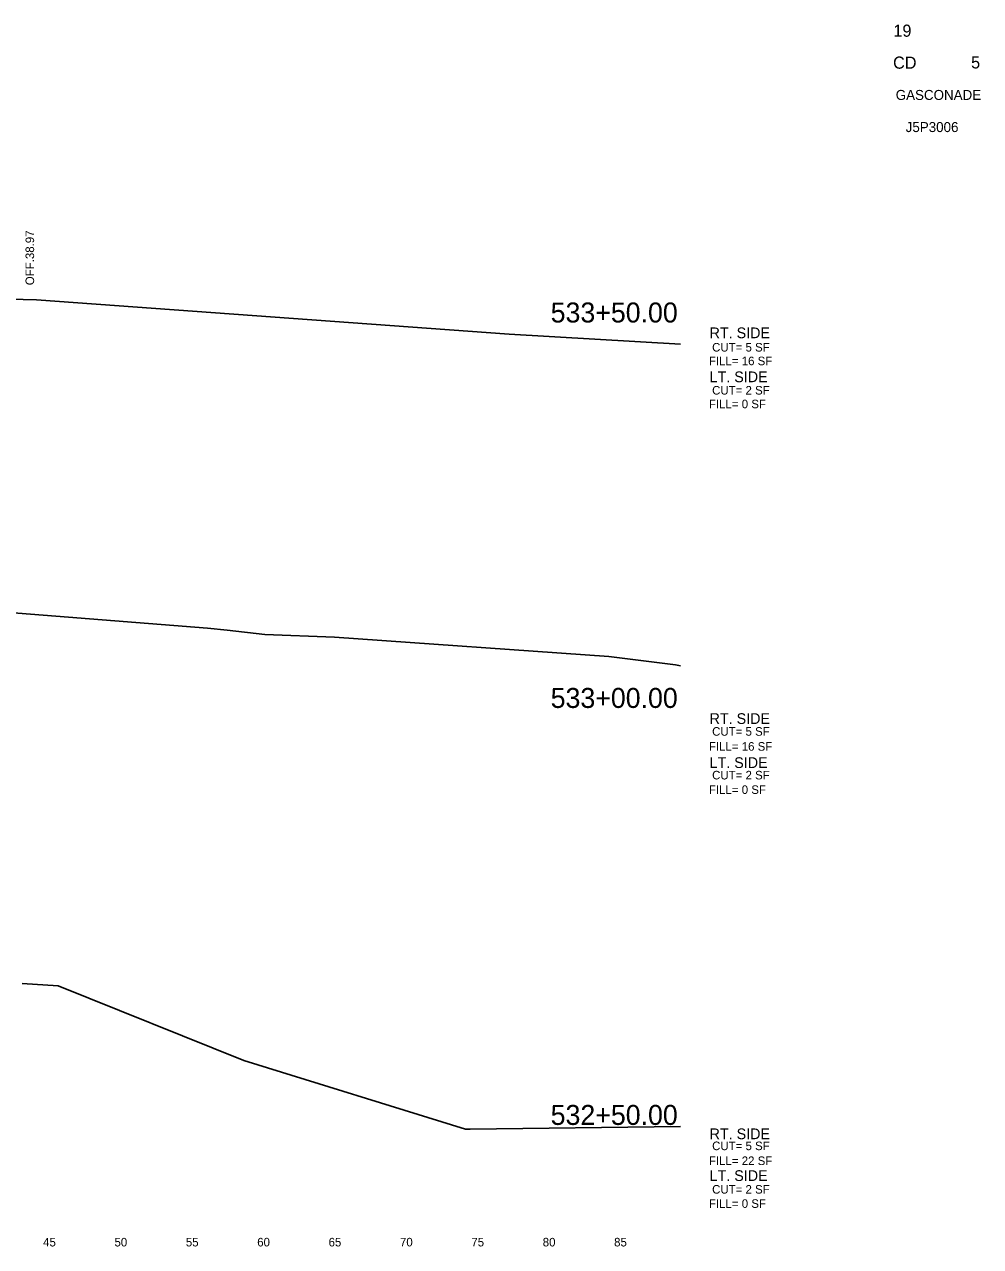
# Model space of a CAD drawing. Extents: x -4 to 359, y 0 to 1436.
# Drawn here: x 87.2 to 154.2, y 600.5 to 686.1 of the extents above; entities that cross this region are included whole.
import ezdxf

# ---------------------------------------------------------------- set-up
doc = ezdxf.new("R2010")
doc.units = 0
for name, color, linetype in [('Common-Title block info', 7, 'Continuous'), ('XS-Existing surface-ground', 7, 'Continuous'), ('XS-Text-earthwork labels', 7, 'Continuous'), ('XS-Text-offset label', 7, 'Continuous'), ('XS-Text-tie elevation', 7, 'Continuous')]:
    doc.layers.add(name, color=color, linetype=linetype)

msp = doc.modelspace()

# ---------------------------------------------------------------- linework, layer by layer
at = {"layer": 'XS-Existing surface-ground'}
for p, q in [((84.816, 666.868), (88.02, 666.783)), ((88.02, 666.783), (121.124, 664.368)), ((121.124, 664.368), (133.13, 663.672)), ((81.884, 645.206), (100.006, 643.781)), ((100.006, 643.781), (101.384, 643.654)), ((101.384, 643.654), (104.005, 643.345)), ((104.005, 643.345), (108.9, 643.149)), ((108.9, 643.149), (128.11, 641.794)), ((128.11, 641.794), (132.794, 641.229)), ((132.794, 641.229), (133.13, 641.145)), ((87.015, 618.901), (89.541, 618.729)), ((89.541, 618.729), (102.537, 613.504)), ((102.537, 613.504), (118.076, 608.704)), ((118.076, 608.704), (118.402, 608.694)), ((118.402, 608.694), (133.13, 608.887))]:
    msp.add_line(p, q, dxfattribs=at)

# ---------------------------------------------------------------- texts
at = {"layer": 'Common-Title block info'}
for s, height, p in [('19', 0.85, (148.047, 685.208)), ('CD', 0.85, (148.025, 682.97)), ('5', 0.85, (153.491, 682.988)), ('GASCONADE', 0.7, (148.211, 680.783)), ('J5P3006', 0.7, (148.909, 678.533))]:
    msp.add_text(s, height=height, dxfattribs=at).set_placement(p)
at = {"layer": 'XS-Text-earthwork labels'}
for s, height, p in [('RT. SIDE', 0.75, (135.171, 664.095)), (' CUT= 5 SF           ', 0.6, (135.125, 663.161)), ('FILL= 16 SF           ', 0.6, (135.125, 662.201)), ('LT. SIDE', 0.75, (135.171, 661.014)), (' CUT= 2 SF           ', 0.6, (135.125, 660.147)), ('FILL= 0 SF           ', 0.6, (135.125, 659.187)), ('RT. SIDE', 0.75, (135.171, 637.078)), (' CUT= 5 SF           ', 0.6, (135.125, 636.252)), ('FILL= 16 SF           ', 0.6, (135.125, 635.204)), ('LT. SIDE', 0.75, (135.171, 633.992)), (' CUT= 2 SF           ', 0.6, (135.125, 633.192)), ('FILL= 0 SF           ', 0.6, (135.125, 632.175)), ('RT. SIDE', 0.75, (135.171, 607.994)), (' CUT= 5 SF           ', 0.6, (135.125, 607.226)), ('FILL= 22 SF           ', 0.6, (135.125, 606.183)), ('LT. SIDE', 0.75, (135.171, 605.068)), (' CUT= 2 SF           ', 0.6, (135.125, 604.181)), ('FILL= 0 SF           ', 0.6, (135.125, 603.184))]:
    msp.add_text(s, height=height, dxfattribs=at).set_placement(p)
at = {"layer": 'XS-Text-offset label'}
for s, height, p in [('           533+50.00           ', 1.4, (118.317, 665.195)), ('           533+00.00           ', 1.4, (118.317, 638.198)), ('           532+50.00           ', 1.4, (118.317, 608.993)), ('           45           ', 0.6, (86.03, 600.482)), ('           50           ', 0.6, (91.03, 600.482)), ('           55           ', 0.6, (96.03, 600.482)), ('           60           ', 0.6, (101.03, 600.482)), ('           65           ', 0.6, (106.03, 600.482)), ('           70           ', 0.6, (111.03, 600.482)), ('           75           ', 0.6, (116.03, 600.482)), ('           80           ', 0.6, (121.03, 600.482)), ('           85           ', 0.6, (126.03, 600.482))]:
    msp.add_text(s, height=height, dxfattribs=at).set_placement(p)
at = {"layer": 'XS-Text-tie elevation'}
msp.add_text('OFF.38.97', height=0.6, rotation=90, dxfattribs=at).set_placement((87.852, 667.807))

doc.saveas('drawing.dxf')
